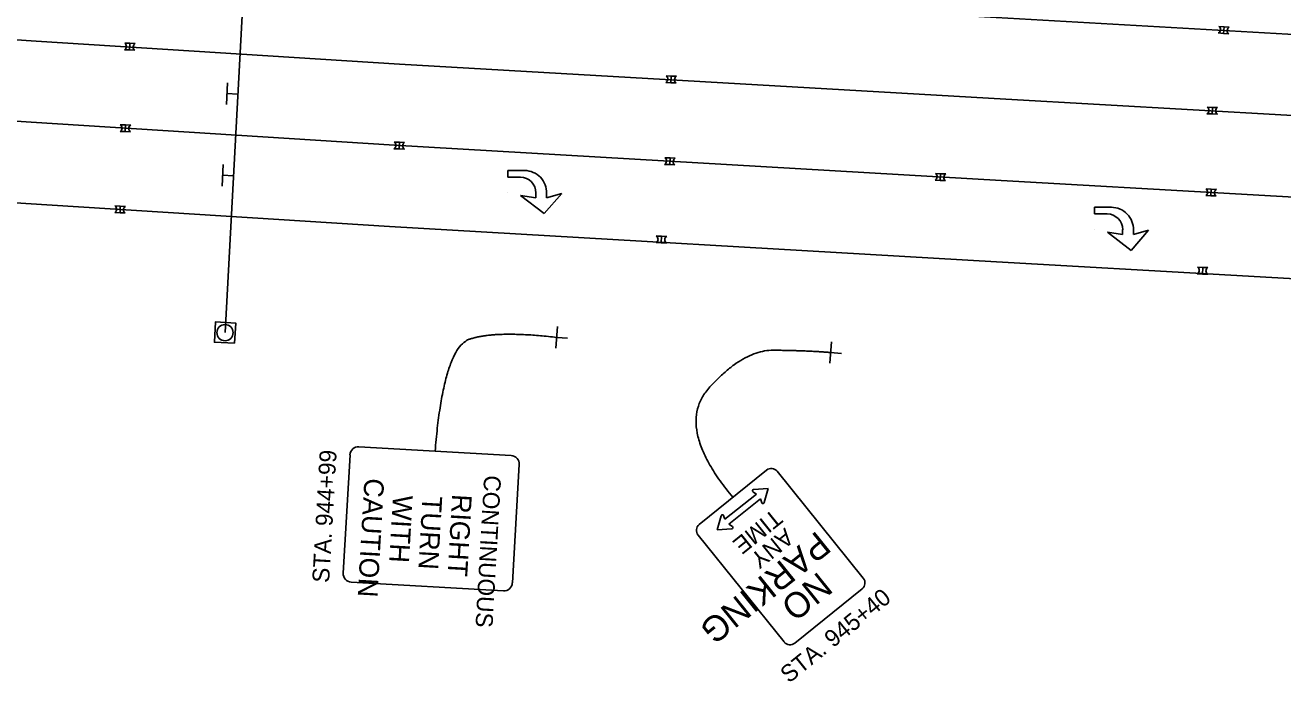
# Model space of a CAD drawing. Extents: x 1847379 to 1850904, y 217032 to 220169.
# Drawn here: x 1848555.2 to 1848740.8, y 218759.2 to 218856.2 of the extents above; entities that cross this region are included whole.
import ezdxf

# ---------------------------------------------------------------- set-up
doc = ezdxf.new("R2010")
doc.units = 0
for name, color, linetype in [('PM_P_Cells', 7, 'Continuous'), ('PM_P_Channelizing_Line', 7, 'Continuous'), ('PM_P_Edge_Line', 7, 'Continuous'), ('PM_P_Lane_Line', 7, 'Continuous'), ('SG_P_Poles', 7, 'Continuous'), ('SN_P_Signs', 7, 'Continuous'), ('SN_X_Public', 7, 'Continuous')]:
    doc.layers.add(name, color=color, linetype=linetype)

msp = doc.modelspace()

# ---------------------------------------------------------------- linework, layer by layer
at = {"layer": 'PM_P_Cells'}
for p, q in [((1848732.12, 218855.94), (1848731.35, 218856.01)), ((1848731.35, 218856.01), (1848732.12, 218855.94)), ((1848731.26, 218855.04), (1848732.03, 218854.97)), ((1848731.26, 218855.04), (1848732.03, 218854.97)), ((1848732.03, 218854.97), (1848732.12, 218855.94)), ((1848732.03, 218854.97), (1848732.8, 218854.9)), ((1848732.12, 218855.94), (1848732.89, 218855.87)), ((1848569.83, 218852.56), (1848570.6, 218852.53)), ((1848569.83, 218852.56), (1848570.6, 218852.53)), ((1848570.64, 218853.51), (1848569.87, 218853.53)), ((1848569.87, 218853.53), (1848570.64, 218853.51)), ((1848570.6, 218852.53), (1848570.64, 218853.51)), ((1848570.6, 218852.53), (1848571.37, 218852.5)), ((1848570.64, 218853.51), (1848571.41, 218853.48)), ((1848650.53, 218848.68), (1848649.76, 218848.71)), ((1848649.76, 218848.71), (1848650.53, 218848.68)), ((1848650.49, 218847.7), (1848650.53, 218848.68)), ((1848650.53, 218848.68), (1848651.3, 218848.65)), ((1848649.72, 218847.73), (1848650.49, 218847.7)), ((1848649.72, 218847.73), (1848650.49, 218847.7)), ((1848650.49, 218847.7), (1848651.26, 218847.67)), ((1848729.59, 218843.12), (1848730.36, 218843.09)), ((1848729.59, 218843.12), (1848730.36, 218843.09)), ((1848730.39, 218844.07), (1848729.62, 218844.1)), ((1848729.62, 218844.1), (1848730.39, 218844.07)), ((1848730.36, 218843.09), (1848730.39, 218844.07)), ((1848730.36, 218843.09), (1848731.13, 218843.06)), ((1848730.39, 218844.07), (1848731.16, 218844.04)), ((1848569.99, 218841.47), (1848569.22, 218841.5)), ((1848569.22, 218841.5), (1848569.99, 218841.47)), ((1848569.96, 218840.5), (1848569.99, 218841.47)), ((1848569.99, 218841.47), (1848570.76, 218841.45)), ((1848569.19, 218840.53), (1848569.96, 218840.5)), ((1848569.19, 218840.53), (1848569.96, 218840.5)), ((1848569.96, 218840.5), (1848570.73, 218840.47)), ((1848609.61, 218837.97), (1848610.38, 218837.94)), ((1848609.61, 218837.97), (1848610.38, 218837.94)), ((1848610.41, 218838.92), (1848609.64, 218838.95)), ((1848609.64, 218838.95), (1848610.41, 218838.92)), ((1848610.38, 218837.94), (1848610.41, 218838.92)), ((1848610.38, 218837.94), (1848611.15, 218837.92)), ((1848610.41, 218838.92), (1848611.18, 218838.89)), ((1848649.54, 218835.65), (1848650.31, 218835.63)), ((1848649.54, 218835.65), (1848650.31, 218835.63)), ((1848650.35, 218836.6), (1848649.58, 218836.63)), ((1848649.58, 218836.63), (1848650.35, 218836.6)), ((1848650.31, 218835.63), (1848650.35, 218836.6)), ((1848650.31, 218835.63), (1848651.08, 218835.6)), ((1848650.35, 218836.6), (1848651.12, 218836.57)), ((1848626.41, 218833.77), (1848626.42, 218834.77)), ((1848628.27, 218833.75), (1848626.41, 218833.77)), ((1848626.42, 218834.77), (1848628.89, 218834.75)), ((1848690.28, 218834.28), (1848689.51, 218834.31)), ((1848689.51, 218834.31), (1848690.28, 218834.28)), ((1848690.24, 218833.3), (1848690.28, 218834.28)), ((1848690.28, 218834.28), (1848691.05, 218834.25)), ((1848689.47, 218833.33), (1848690.24, 218833.3)), ((1848689.47, 218833.33), (1848690.24, 218833.3)), ((1848690.24, 218833.3), (1848691.01, 218833.28)), ((1848730.22, 218832), (1848729.45, 218832.03)), ((1848729.45, 218832.03), (1848730.22, 218832)), ((1848730.18, 218831.03), (1848730.22, 218832)), ((1848730.22, 218832), (1848730.99, 218831.97)), ((1848626.38, 218831.44), (1848626.38, 218831.44)), ((1848631.8, 218828.39), (1848628.3, 218831.09)), ((1848628.3, 218831.09), (1848630.54, 218830.73)), ((1848630.54, 218830.73), (1848630.54, 218831.43)), ((1848634.38, 218831.36), (1848631.8, 218828.39)), ((1848632.14, 218831.38), (1848632.14, 218830.72)), ((1848632.14, 218830.72), (1848634.38, 218831.36)), ((1848634.38, 218831.36), (1848634.38, 218831.36)), ((1848729.41, 218831.05), (1848730.18, 218831.03)), ((1848729.41, 218831.05), (1848730.18, 218831.03)), ((1848730.18, 218831.03), (1848730.95, 218831)), ((1848568.41, 218828.55), (1848569.18, 218828.52)), ((1848568.41, 218828.55), (1848569.18, 218828.52)), ((1848569.21, 218829.5), (1848568.44, 218829.53)), ((1848568.44, 218829.53), (1848569.21, 218829.5)), ((1848569.18, 218828.52), (1848569.21, 218829.5)), ((1848569.18, 218828.52), (1848569.95, 218828.5)), ((1848569.21, 218829.5), (1848569.98, 218829.47)), ((1848713.01, 218828.36), (1848713.01, 218829.36)), ((1848713.01, 218829.36), (1848715.49, 218829.34)), ((1848714.87, 218828.34), (1848713.01, 218828.36)), ((1848649.1, 218825.07), (1848648.32, 218825.09)), ((1848648.32, 218825.09), (1848649.1, 218825.07)), ((1848649.06, 218824.09), (1848649.1, 218825.07)), ((1848649.1, 218825.07), (1848649.87, 218825.04)), ((1848712.98, 218826.03), (1848712.98, 218826.03)), ((1848718.39, 218822.98), (1848714.9, 218825.68)), ((1848714.9, 218825.68), (1848717.14, 218825.32)), ((1848717.14, 218825.32), (1848717.14, 218826.03)), ((1848720.98, 218825.95), (1848718.39, 218822.98)), ((1848718.74, 218825.97), (1848718.74, 218825.31)), ((1848718.74, 218825.31), (1848720.98, 218825.95)), ((1848720.98, 218825.95), (1848720.98, 218825.95)), ((1848648.29, 218824.12), (1848649.06, 218824.09)), ((1848648.29, 218824.12), (1848649.06, 218824.09)), ((1848649.06, 218824.09), (1848649.83, 218824.06)), ((1848728.16, 218819.52), (1848728.93, 218819.49)), ((1848728.16, 218819.52), (1848728.93, 218819.49)), ((1848728.97, 218820.47), (1848728.19, 218820.5)), ((1848728.19, 218820.5), (1848728.97, 218820.47)), ((1848728.93, 218819.49), (1848728.97, 218820.47)), ((1848728.93, 218819.49), (1848729.7, 218819.46)), ((1848728.97, 218820.47), (1848729.74, 218820.44))]:
    msp.add_line(p, q, dxfattribs=at)
for centre, radius, start, end in [((1848731.01, 218855.55), 0.576, 296.8063, 52.8586), ((1848731.01, 218855.55), 0.576, 296.8063, 52.8586), ((1848733.15, 218855.36), 0.576, 116.8063, 232.8586), ((1848569.55, 218853.06), 0.576, 299.9028, 55.9551), ((1848569.55, 218853.06), 0.576, 299.9028, 55.9551), ((1848571.7, 218852.98), 0.576, 119.9028, 235.9551), ((1848649.44, 218848.23), 0.576, 299.9028, 55.9551), ((1848649.44, 218848.23), 0.576, 299.9028, 55.9551), ((1848651.59, 218848.15), 0.576, 119.9028, 235.9551), ((1848729.3, 218843.62), 0.576, 299.9028, 55.9551), ((1848729.3, 218843.62), 0.576, 299.9028, 55.9551), ((1848731.45, 218843.54), 0.576, 119.9028, 235.9551), ((1848568.9, 218841.02), 0.576, 299.9028, 55.9551), ((1848568.9, 218841.02), 0.576, 299.9028, 55.9551), ((1848571.05, 218840.95), 0.576, 119.9028, 235.9551), ((1848609.32, 218838.47), 0.576, 299.9028, 55.9551), ((1848609.32, 218838.47), 0.576, 299.9028, 55.9551), ((1848611.47, 218838.39), 0.576, 119.9028, 235.9551), ((1848649.25, 218836.15), 0.576, 299.9028, 55.9551), ((1848649.25, 218836.15), 0.576, 299.9028, 55.9551), ((1848651.4, 218836.07), 0.576, 119.9028, 235.9551), ((1848628.25, 218831.46), 2.3, 359.4564, 89.4564), ((1848628.86, 218831.47), 3.28, 358.5479, 89.4564), ((1848689.19, 218833.83), 0.576, 299.9028, 55.9551), ((1848689.19, 218833.83), 0.576, 299.9028, 55.9551), ((1848691.34, 218833.75), 0.576, 119.9028, 235.9551), ((1848729.12, 218831.55), 0.576, 299.9028, 55.9551), ((1848729.12, 218831.55), 0.576, 299.9028, 55.9551), ((1848731.27, 218831.48), 0.576, 119.9028, 235.9551), ((1848568.12, 218829.05), 0.576, 299.9028, 55.9551), ((1848568.12, 218829.05), 0.576, 299.9028, 55.9551), ((1848570.27, 218828.97), 0.576, 119.9028, 235.9551), ((1848714.85, 218826.05), 2.3, 359.4564, 89.4564), ((1848715.46, 218826.06), 3.28, 358.5479, 89.4564), ((1848648, 218824.62), 0.576, 299.9028, 55.9551), ((1848648, 218824.62), 0.576, 299.9028, 55.9551), ((1848650.15, 218824.54), 0.576, 119.9028, 235.9551), ((1848727.87, 218820.02), 0.576, 299.9028, 55.9551), ((1848727.87, 218820.02), 0.576, 299.9028, 55.9551), ((1848730.02, 218819.94), 0.576, 119.9028, 235.9551)]:
    msp.add_arc(centre, radius, start, end, dxfattribs=at)
at = {"layer": 'PM_P_Channelizing_Line'}
msp.add_lwpolyline([(1848893.84, 218822.16), (1848768.36, 218829.35), (1848699.2, 218833.28), (1848609.68, 218838.48), (1848556.05, 218841.87), (1848494.16, 218846.05), (1848452.97, 218848.49), (1848409.58, 218851.32)], dxfattribs=at)
at = {"layer": 'PM_P_Edge_Line'}
msp.add_lwpolyline([(1848816.62, 218814.57), (1848767.67, 218817.37), (1848698.52, 218821.29), (1848608.95, 218826.5), (1848555.27, 218829.89), (1848493.4, 218834.07), (1848452.22, 218836.51), (1848408.8, 218839.34)], dxfattribs=at)
at = {"layer": 'PM_P_Lane_Line'}
msp.add_line((1848558.52, 218865.36), (1848836.12, 218849.43), dxfattribs=at)
msp.add_lwpolyline([(1848835.23, 218837.54), (1848769.04, 218841.33), (1848699.89, 218845.26), (1848610.41, 218850.46), (1848556.83, 218853.84), (1848494.92, 218858.02), (1848453.72, 218860.46), (1848410.36, 218863.29)], dxfattribs=at)
at = {"layer": 'SG_P_Poles'}
msp.add_lwpolyline([(1848586.1, 218809.27), (1848586.26, 218812.26), (1848583.27, 218812.42), (1848583.11, 218809.43)], close=True, dxfattribs=at)
msp.add_circle((1848584.68, 218810.84), 1.2, dxfattribs=at)
at = {"layer": 'SN_P_Signs'}
for p, q in [((1848584.68, 218810.84), (1848590.57, 218920.69)), ((1848584.88, 218844.5), (1848585.06, 218847.69)), ((1848584.97, 218846.09), (1848586.57, 218846.01)), ((1848584.24, 218832.45), (1848584.41, 218835.65)), ((1848584.33, 218834.05), (1848585.92, 218833.97))]:
    msp.add_line(p, q, dxfattribs=at)
at = {"layer": 'SN_X_Public'}
for p, q in [((1848633.51, 218808.54), (1848633.75, 218811.73)), ((1848633.63, 218810.14), (1848635.23, 218810.02)), ((1848673.93, 218806.32), (1848674.17, 218809.51)), ((1848674.05, 218807.91), (1848675.65, 218807.79)), ((1848662.59, 218787.37), (1848663.09, 218787.04)), ((1848664.84, 218787.85), (1848662.68, 218787.71)), ((1848664.24, 218785.77), (1848664.84, 218787.85)), ((1848659.05, 218782.58), (1848663.68, 218786.31)), ((1848663.68, 218786.31), (1848663.68, 218786.31)), ((1848663.68, 218786.31), (1848663.9, 218785.75)), ((1848657.9, 218783.85), (1848657.3, 218781.77)), ((1848658.46, 218783.31), (1848658.24, 218783.86)), ((1848661.07, 218784.81), (1848661.07, 218784.81)), ((1848657.3, 218781.77), (1848659.46, 218781.91)), ((1848659.55, 218782.25), (1848659.05, 218782.58)), ((1848659.05, 218782.58), (1848659.05, 218782.58))]:
    msp.add_line(p, q, dxfattribs=at)
for points in [[(1848626.91, 218792.72), (1848604.45, 218794.01)], [(1848603.13, 218792.83), (1848602.12, 218775.36)], [(1848627.08, 218773.93), (1848628.09, 218791.4)], [(1848664.58, 218790.56), (1848654.66, 218782.56)], [(1848678.87, 218774.63), (1848666.17, 218790.39)], [(1848663.09, 218787.04), (1848658.46, 218783.31)], [(1848654.49, 218780.98), (1848667.19, 218765.22)], [(1848603.3, 218774.04), (1848625.76, 218772.75)], [(1848668.78, 218765.05), (1848678.7, 218773.05)]]:
    msp.add_lwpolyline(points, dxfattribs=at)
for centre, radius, start, end in [((1848604.37, 218792.76), 1.25, 86.7151, 176.7151), ((1848626.84, 218791.47), 1.25, 356.7151, 86.7151), ((1848665.29, 218789.69), 1.12, 38.8676, 128.8676), ((1848662.7, 218787.52), 0.182, 93.7884, 236.5054), ((1848664.07, 218785.82), 0.182, 201.2298, 343.9469), ((1848658.07, 218783.8), 0.182, 21.2298, 163.9469), ((1848655.36, 218781.69), 1.12, 128.8676, 218.8676), ((1848659.45, 218782.09), 0.182, 273.7884, 56.5054), ((1848603.37, 218775.29), 1.25, 176.7151, 266.7151), ((1848678, 218773.92), 1.12, 308.8676, 38.8676), ((1848625.83, 218774), 1.25, 266.7151, 356.7151), ((1848668.07, 218765.92), 1.12, 218.8676, 308.8676)]:
    msp.add_arc(centre, radius, start, end, dxfattribs=at)
for points in [[(1848633.63, 218810.14), (1848624.62, 218811.19), (1848616.93, 218808.57), (1848615.68, 218793.36)], [(1848674.05, 218807.91), (1848670.17, 218808.22), (1848661.07, 218808.27), (1848651.01, 218796.93), (1848659.62, 218786.56)]]:
    msp.add_open_spline(points, degree=2, dxfattribs=at)

# ---------------------------------------------------------------- texts
for s, height, rotation, p in [('STA. 944+99', 2.5, 86.7151, (1848600.04, 218773.9)), ('CAUTION', 2.915, 266.7151, (1848605.26, 218789.42)), ('CONTINUOUS', 2.5, 266.7151, (1848622.93, 218789.86)), ('WITH', 2.915, 266.7151, (1848609.48, 218786.93)), ('TURN', 2.915, 266.7151, (1848613.83, 218786.79)), ('RIGHT', 2.915, 266.7151, (1848618.2, 218787.07)), ('TIME', 2.5, 218.8676, (1848665.62, 218784.97)), ('ANY', 2.5, 218.8676, (1848667.32, 218782.14)), ('PARKING', 3.75, 218.8676, (1848672.04, 218781.72)), ('NO', 3.75, 218.8676, (1848672.29, 218775.7)), ('STA. 945+40', 2.5, 38.8676, (1848667.9, 218759.05))]:
    msp.add_text(s, height=height, rotation=rotation, dxfattribs=at).set_placement(p)

doc.saveas('drawing.dxf')
